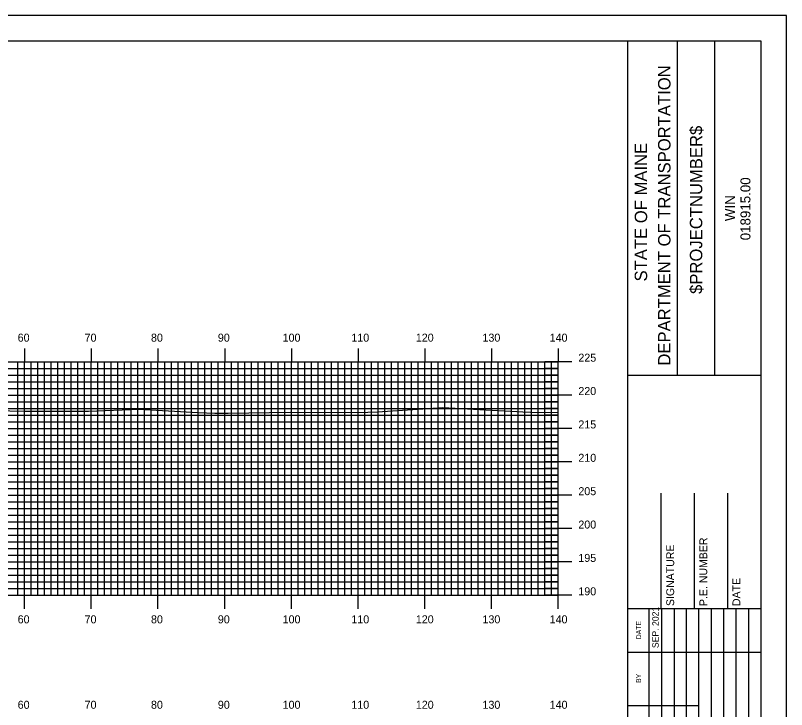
# Model space of a CAD drawing. Extents: x 1800355 to 1800699, y 442591 to 442811.
# Drawn here: x 1800579.7 to 1800695.2, y 442706.6 to 442810.5 of the extents above; entities that cross this region are included whole.
import ezdxf

# ---------------------------------------------------------------- set-up
doc = ezdxf.new("R2010")
doc.units = 0
for name, color, linetype in [('BORDER', 7, 'Continuous'), ('H_V ANNOTATION', 7, 'Continuous'), ('MAJOR', 7, 'Continuous'), ('MINOR', 7, 'Continuous'), ('PLOT BOUNDARY', 7, 'Continuous'), ('S_Roadway_Centerline', 7, 'Continuous')]:
    doc.layers.add(name, color=color, linetype=linetype)

msp = doc.modelspace()

# ---------------------------------------------------------------- linework, layer by layer
at = {"layer": 'BORDER'}
for p, q in [((1800671.44, 442596.67), (1800671.44, 442806.67)), ((1800678.89, 442756.66), (1800678.89, 442806.66)), ((1800684.48, 442756.66), (1800684.48, 442806.66)), ((1800671.44, 442756.65), (1800691.44, 442756.65)), ((1800676.44, 442721.67), (1800676.44, 442738.97)), ((1800681.44, 442721.67), (1800681.44, 442738.97)), ((1800686.44, 442721.67), (1800686.44, 442738.97)), ((1800671.44, 442721.67), (1800691.44, 442721.67))]:
    msp.add_line(p, q, dxfattribs=at)
msp.add_lwpolyline([(1800371.44, 442596.67), (1800691.44, 442596.67), (1800691.44, 442806.67), (1800371.44, 442806.67)], close=True, dxfattribs=at)
for points in [[(1800674.67, 442715.17), (1800674.67, 442721.67)], [(1800676.53, 442686.68), (1800676.53, 442721.67)], [(1800678.39, 442721.67), (1800678.39, 442686.68)], [(1800680.26, 442686.68), (1800680.26, 442721.67)], [(1800682.12, 442686.68), (1800682.12, 442721.67)], [(1800683.98, 442686.68), (1800683.98, 442721.67)], [(1800685.85, 442686.68), (1800685.85, 442721.67)], [(1800687.71, 442686.68), (1800687.71, 442721.67)], [(1800689.57, 442686.68), (1800689.57, 442721.67)], [(1800674.67, 442686.68), (1800674.67, 442720.26)], [(1800671.44, 442715.17), (1800691.44, 442715.17)], [(1800671.44, 442707.17), (1800674.67, 442707.17)], [(1800674.67, 442707.17), (1800682.12, 442707.17)]]:
    msp.add_lwpolyline(points, dxfattribs=at)
at = {"layer": 'MAJOR'}
for p, q in [((1800581.04, 442760.67), (1800581.04, 442758.67)), ((1800591.04, 442760.67), (1800591.04, 442758.67)), ((1800601.04, 442760.67), (1800601.04, 442758.67)), ((1800611.04, 442760.67), (1800611.04, 442758.67)), ((1800621.04, 442760.67), (1800621.04, 442758.67)), ((1800631.04, 442760.67), (1800631.04, 442758.67)), ((1800641.04, 442760.67), (1800641.04, 442758.67)), ((1800651.04, 442760.67), (1800651.04, 442758.67)), ((1800661.04, 442760.67), (1800661.04, 442758.67)), ((1800381.04, 442758.67), (1800661.04, 442758.67)), ((1800381.04, 442758.67), (1800661.04, 442758.67)), ((1800581.04, 442723.67), (1800581.04, 442758.67)), ((1800591.04, 442723.67), (1800591.04, 442758.67)), ((1800601.04, 442723.67), (1800601.04, 442758.67)), ((1800611.04, 442723.67), (1800611.04, 442758.67)), ((1800621.04, 442723.67), (1800621.04, 442758.67)), ((1800631.04, 442723.67), (1800631.04, 442758.67)), ((1800641.04, 442723.67), (1800641.04, 442758.67)), ((1800651.04, 442723.67), (1800651.04, 442758.67)), ((1800663.04, 442758.67), (1800659.03, 442758.67)), ((1800661.04, 442723.67), (1800661.04, 442758.67)), ((1800661.04, 442723.67), (1800661.04, 442758.67)), ((1800381.04, 442753.67), (1800661.04, 442753.67)), ((1800663.04, 442753.67), (1800659.03, 442753.67)), ((1800381.04, 442748.67), (1800661.04, 442748.67)), ((1800663.04, 442748.67), (1800659.03, 442748.67)), ((1800381.04, 442743.67), (1800661.04, 442743.67)), ((1800663.04, 442743.67), (1800659.03, 442743.67)), ((1800381.04, 442738.67), (1800661.04, 442738.67)), ((1800663.04, 442738.67), (1800659.03, 442738.67)), ((1800381.04, 442733.67), (1800661.04, 442733.67)), ((1800663.04, 442733.67), (1800659.03, 442733.67)), ((1800381.04, 442728.67), (1800661.04, 442728.67)), ((1800663.04, 442728.67), (1800659.03, 442728.67)), ((1800381.04, 442723.67), (1800661.04, 442723.67)), ((1800381.04, 442723.67), (1800661.04, 442723.67)), ((1800581.04, 442721.66), (1800581.04, 442723.67)), ((1800591.04, 442721.66), (1800591.04, 442723.67)), ((1800601.04, 442721.66), (1800601.04, 442723.67)), ((1800611.04, 442721.66), (1800611.04, 442723.67)), ((1800621.04, 442721.66), (1800621.04, 442723.67)), ((1800631.04, 442721.66), (1800631.04, 442723.67)), ((1800641.04, 442721.66), (1800641.04, 442723.67)), ((1800651.04, 442721.66), (1800651.04, 442723.67)), ((1800663.04, 442723.67), (1800659.03, 442723.67)), ((1800661.04, 442721.66), (1800661.04, 442723.67))]:
    msp.add_line(p, q, dxfattribs=at)
at = {"layer": 'MINOR'}
for p, q in [((1800381.04, 442757.67), (1800661.04, 442757.67)), ((1800580.04, 442723.67), (1800580.04, 442758.67)), ((1800582.04, 442723.67), (1800582.04, 442758.67)), ((1800583.04, 442723.67), (1800583.04, 442758.67)), ((1800584.04, 442723.67), (1800584.04, 442758.67)), ((1800585.04, 442723.67), (1800585.04, 442758.67)), ((1800586.04, 442723.67), (1800586.04, 442758.67)), ((1800587.04, 442723.67), (1800587.04, 442758.67)), ((1800588.04, 442723.67), (1800588.04, 442758.67)), ((1800589.04, 442723.67), (1800589.04, 442758.67)), ((1800590.04, 442723.67), (1800590.04, 442758.67)), ((1800592.04, 442723.67), (1800592.04, 442758.67)), ((1800593.04, 442723.67), (1800593.04, 442758.67)), ((1800594.04, 442723.67), (1800594.04, 442758.67)), ((1800595.04, 442723.67), (1800595.04, 442758.67)), ((1800596.04, 442723.67), (1800596.04, 442758.67)), ((1800597.04, 442723.67), (1800597.04, 442758.67)), ((1800598.04, 442723.67), (1800598.04, 442758.67)), ((1800599.04, 442723.67), (1800599.04, 442758.67)), ((1800600.04, 442723.67), (1800600.04, 442758.67)), ((1800602.04, 442723.67), (1800602.04, 442758.67)), ((1800603.04, 442723.67), (1800603.04, 442758.67)), ((1800604.04, 442723.67), (1800604.04, 442758.67)), ((1800605.04, 442723.67), (1800605.04, 442758.67)), ((1800606.04, 442723.67), (1800606.04, 442758.67)), ((1800607.04, 442723.67), (1800607.04, 442758.67)), ((1800608.04, 442723.67), (1800608.04, 442758.67)), ((1800609.04, 442723.67), (1800609.04, 442758.67)), ((1800610.04, 442723.67), (1800610.04, 442758.67)), ((1800612.04, 442723.67), (1800612.04, 442758.67)), ((1800613.04, 442723.67), (1800613.04, 442758.67)), ((1800614.04, 442723.67), (1800614.04, 442758.67)), ((1800615.04, 442723.67), (1800615.04, 442758.67)), ((1800616.04, 442723.67), (1800616.04, 442758.67)), ((1800617.04, 442723.67), (1800617.04, 442758.67)), ((1800618.04, 442723.67), (1800618.04, 442758.67)), ((1800619.04, 442723.67), (1800619.04, 442758.67)), ((1800620.04, 442723.67), (1800620.04, 442758.67)), ((1800622.04, 442723.67), (1800622.04, 442758.67)), ((1800623.04, 442723.67), (1800623.04, 442758.67)), ((1800624.04, 442723.67), (1800624.04, 442758.67)), ((1800625.04, 442723.67), (1800625.04, 442758.67)), ((1800626.04, 442723.67), (1800626.04, 442758.67)), ((1800627.04, 442723.67), (1800627.04, 442758.67)), ((1800628.04, 442723.67), (1800628.04, 442758.67)), ((1800629.04, 442723.67), (1800629.04, 442758.67)), ((1800630.04, 442723.67), (1800630.04, 442758.67)), ((1800632.04, 442723.67), (1800632.04, 442758.67)), ((1800633.04, 442723.67), (1800633.04, 442758.67)), ((1800634.04, 442723.67), (1800634.04, 442758.67)), ((1800635.04, 442723.67), (1800635.04, 442758.67)), ((1800636.04, 442723.67), (1800636.04, 442758.67)), ((1800637.04, 442723.67), (1800637.04, 442758.67)), ((1800638.04, 442723.67), (1800638.04, 442758.67)), ((1800639.04, 442723.67), (1800639.04, 442758.67)), ((1800640.04, 442723.67), (1800640.04, 442758.67)), ((1800642.04, 442723.67), (1800642.04, 442758.67)), ((1800643.04, 442723.67), (1800643.04, 442758.67)), ((1800644.04, 442723.67), (1800644.04, 442758.67)), ((1800645.04, 442723.67), (1800645.04, 442758.67)), ((1800646.04, 442723.67), (1800646.04, 442758.67)), ((1800647.04, 442723.67), (1800647.04, 442758.67)), ((1800648.04, 442723.67), (1800648.04, 442758.67)), ((1800649.04, 442723.67), (1800649.04, 442758.67)), ((1800650.04, 442723.67), (1800650.04, 442758.67)), ((1800652.04, 442723.67), (1800652.04, 442758.67)), ((1800653.04, 442723.67), (1800653.04, 442758.67)), ((1800654.04, 442723.67), (1800654.04, 442758.67)), ((1800655.04, 442723.67), (1800655.04, 442758.67)), ((1800656.04, 442723.67), (1800656.04, 442758.67)), ((1800657.04, 442723.67), (1800657.04, 442758.67)), ((1800658.04, 442723.67), (1800658.04, 442758.67)), ((1800661.04, 442757.67), (1800659.03, 442757.67)), ((1800659.04, 442723.67), (1800659.04, 442758.67)), ((1800660.04, 442723.67), (1800660.04, 442758.67)), ((1800381.04, 442756.67), (1800661.04, 442756.67)), ((1800661.04, 442756.67), (1800659.03, 442756.67)), ((1800381.04, 442755.67), (1800661.04, 442755.67)), ((1800661.04, 442755.67), (1800659.03, 442755.67)), ((1800381.04, 442754.67), (1800661.04, 442754.67)), ((1800661.04, 442754.67), (1800659.03, 442754.67)), ((1800381.04, 442752.67), (1800661.04, 442752.67)), ((1800661.04, 442752.67), (1800659.03, 442752.67)), ((1800381.04, 442751.67), (1800661.04, 442751.67)), ((1800381.04, 442750.67), (1800661.04, 442750.67)), ((1800661.04, 442751.67), (1800659.03, 442751.67)), ((1800661.04, 442750.67), (1800659.03, 442750.67)), ((1800381.04, 442749.67), (1800661.04, 442749.67)), ((1800661.04, 442749.67), (1800659.03, 442749.67)), ((1800381.04, 442747.67), (1800661.04, 442747.67)), ((1800661.04, 442747.67), (1800659.03, 442747.67)), ((1800381.04, 442746.67), (1800661.04, 442746.67)), ((1800661.04, 442746.67), (1800659.03, 442746.67)), ((1800381.04, 442745.67), (1800661.04, 442745.67)), ((1800661.04, 442745.67), (1800659.03, 442745.67)), ((1800381.04, 442744.67), (1800661.04, 442744.67)), ((1800661.04, 442744.67), (1800659.03, 442744.67)), ((1800381.04, 442742.67), (1800661.04, 442742.67)), ((1800661.04, 442742.67), (1800659.03, 442742.67)), ((1800381.04, 442741.67), (1800661.04, 442741.67)), ((1800661.04, 442741.67), (1800659.03, 442741.67)), ((1800381.04, 442740.67), (1800661.04, 442740.67)), ((1800661.04, 442740.67), (1800659.03, 442740.67)), ((1800381.04, 442739.67), (1800661.04, 442739.67)), ((1800661.04, 442739.67), (1800659.03, 442739.67)), ((1800381.04, 442737.67), (1800661.04, 442737.67)), ((1800661.04, 442737.67), (1800659.03, 442737.67)), ((1800381.04, 442736.67), (1800661.04, 442736.67)), ((1800381.04, 442735.67), (1800661.04, 442735.67)), ((1800661.04, 442736.67), (1800659.03, 442736.67)), ((1800661.04, 442735.67), (1800659.03, 442735.67)), ((1800381.04, 442734.67), (1800661.04, 442734.67)), ((1800661.04, 442734.67), (1800659.03, 442734.67)), ((1800381.04, 442732.67), (1800661.04, 442732.67)), ((1800661.04, 442732.67), (1800659.03, 442732.67)), ((1800381.04, 442731.67), (1800661.04, 442731.67)), ((1800661.04, 442731.67), (1800659.03, 442731.67)), ((1800381.04, 442730.67), (1800661.04, 442730.67)), ((1800661.04, 442730.67), (1800659.03, 442730.67)), ((1800381.04, 442729.67), (1800661.04, 442729.67)), ((1800661.04, 442729.67), (1800659.03, 442729.67)), ((1800381.04, 442727.67), (1800661.04, 442727.67)), ((1800661.04, 442727.67), (1800659.03, 442727.67)), ((1800381.04, 442726.67), (1800661.04, 442726.67)), ((1800661.04, 442726.67), (1800659.03, 442726.67)), ((1800381.04, 442725.67), (1800661.04, 442725.67)), ((1800661.04, 442725.67), (1800659.03, 442725.67)), ((1800381.04, 442724.67), (1800661.04, 442724.67)), ((1800661.04, 442724.67), (1800659.03, 442724.67))]:
    msp.add_line(p, q, dxfattribs=at)
at = {"layer": 'PLOT BOUNDARY'}
msp.add_lwpolyline([(1800355.25, 442590.55), (1800695.25, 442590.55), (1800695.25, 442810.55), (1800355.25, 442810.55)], close=True, dxfattribs=at)
at = {"layer": 'S_Roadway_Centerline'}
msp.add_lwpolyline([(1800574.34, 442751.41), (1800581.1, 442751.24), (1800590.61, 442751.27), (1800598.18, 442751.54), (1800607.06, 442751.04), (1800609.54, 442750.98), (1800611.58, 442750.94), (1800620.83, 442751.1), (1800631.06, 442751.05), (1800633.93, 442751.14), (1800643.71, 442751.79), (1800655.73, 442751.14), (1800656.88, 442751.11), (1800661.04, 442751.06)], dxfattribs=at)

# ---------------------------------------------------------------- texts
at = {"layer": 'BORDER'}
for s, height, p in [('DEPARTMENT OF TRANSPORTATION', 1.8635, (1800677.85, 442758.08)), ('$PROJECTNUMBER$', 1.8635, (1800682.62, 442768.82)), ('STATE OF MAINE', 1.8635, (1800674.35, 442770.69)), ('018915.00', 1.491, (1800689.83, 442776.86)), ('WIN', 1.491, (1800687.51, 442779.73)), ('P.E. NUMBER', 1.1811, (1800683.36, 442722.06)), ('SIGNATURE', 1.181, (1800678.4, 442722.06)), ('DATE', 1.181, (1800688.32, 442722.06)), ('SEP. 2021', 0.969, (1800676.08, 442715.76)), ('DATE', 0.743, (1800673.44, 442717.08)), ('BY', 0.743, (1800673.44, 442710.54))]:
    msp.add_text(s, height=height, rotation=90, dxfattribs=at).set_placement(p)
at = {"layer": 'H_V ANNOTATION'}
for s, p in [('60', (1800580.01, 442761.67)), ('70', (1800590.04, 442761.67)), ('80', (1800599.99, 442761.67)), ('90', (1800610.01, 442761.67)), ('100', (1800619.72, 442761.67)), ('110', (1800630.02, 442761.67)), ('120', (1800639.68, 442761.67)), ('130', (1800649.67, 442761.67)), ('140', (1800659.74, 442761.67)), ('225', (1800664.04, 442758.67)), ('220', (1800664.04, 442753.67)), ('215', (1800664.04, 442748.67)), ('210', (1800664.04, 442743.67)), ('205', (1800664.04, 442738.67)), ('200', (1800664.04, 442733.67)), ('195', (1800664.04, 442728.67)), ('190', (1800664.04, 442723.67)), ('60', (1800580.01, 442719.47)), ('70', (1800590.04, 442719.47)), ('80', (1800599.99, 442719.47)), ('90', (1800610.01, 442719.47)), ('100', (1800619.72, 442719.47)), ('110', (1800630.02, 442719.47)), ('120', (1800639.68, 442719.47)), ('130', (1800649.67, 442719.47)), ('140', (1800659.74, 442719.47)), ('60', (1800580.01, 442706.67)), ('70', (1800590.04, 442706.67)), ('80', (1800599.99, 442706.67)), ('90', (1800610.01, 442706.67)), ('100', (1800619.72, 442706.67)), ('110', (1800630.02, 442706.67)), ('120', (1800639.68, 442706.67)), ('130', (1800649.67, 442706.67)), ('140', (1800659.74, 442706.67))]:
    msp.add_text(s, height=1.2, dxfattribs=at).set_placement(p)

doc.saveas('drawing.dxf')
